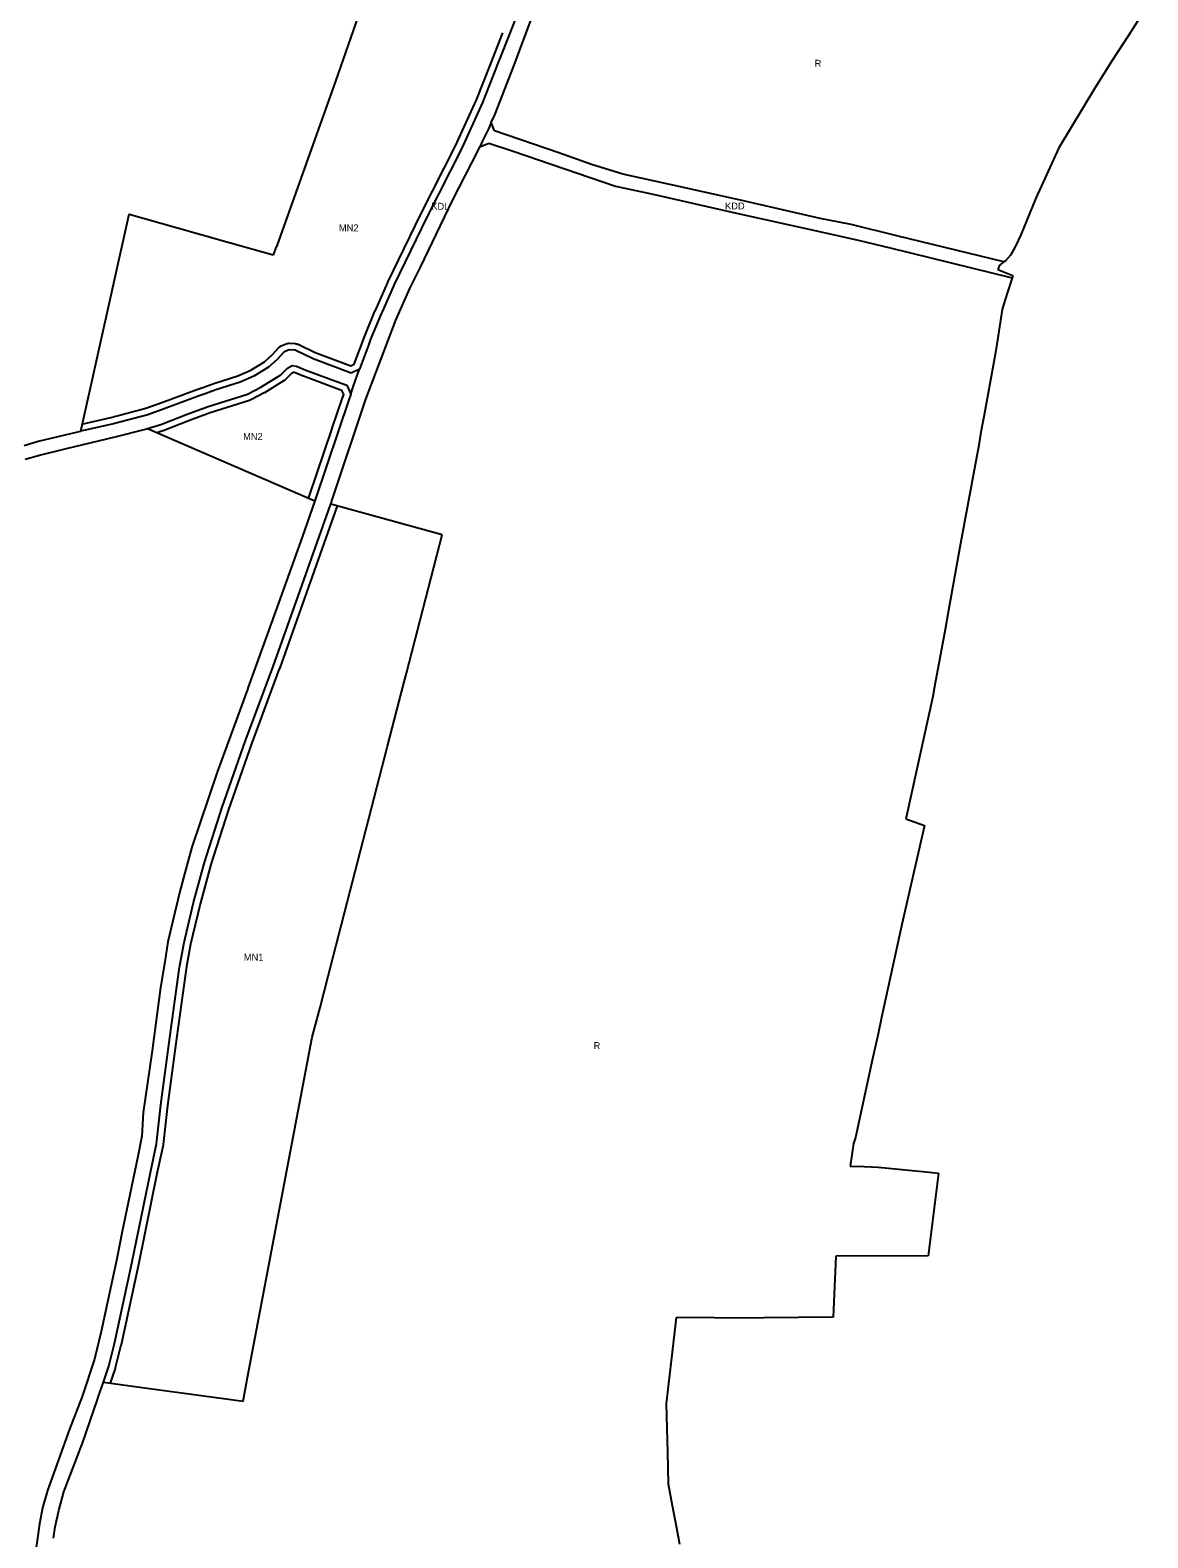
# Model space of a CAD drawing. Extents: x 7435758 to 7439981, y 5550649 to 5554049.
# Drawn here: x 7439010 to 7439847, y 5551717 to 5552845 of the extents above; entities that cross this region are included whole.
import ezdxf

# ---------------------------------------------------------------- set-up
doc = ezdxf.new("R2010")
doc.units = 0
for name, color, linetype in [('linie_rozgraniczające', 7, 'Continuous'), ('linie_zabudowy_nieprzekraczalne', 7, 'Continuous'), ('oznaczenia_przeznaczen', 7, 'Continuous')]:
    doc.layers.add(name, color=color, linetype=linetype)

msp = doc.modelspace()

# ---------------------------------------------------------------- linework, layer by layer
at = {"layer": 'linie_rozgraniczające'}
for p, q in [((7439255.67, 5552855.96), (7439238.89, 5552807.33)), ((7439846.87, 5552864.2), (7439832.42, 5552841.4)), ((7439373.25, 5552853.51), (7439368.77, 5552842.02)), ((7439372.45, 5552819.32), (7439385.2, 5552853.46)), ((7439368.77, 5552842.02), (7439362.63, 5552826.25)), ((7439832.42, 5552841.4), (7439820.12, 5552822.79)), ((7439362.63, 5552826.25), (7439359.42, 5552818.09)), ((7439820.12, 5552822.79), (7439807.09, 5552802.1)), ((7439359.39, 5552818.03), (7439348.82, 5552791.18)), ((7439358.05, 5552781.97), (7439372.45, 5552819.32)), ((7439359.42, 5552818.09), (7439359.39, 5552818.03)), ((7439238.89, 5552807.33), (7439194.84, 5552684.02)), ((7439807.09, 5552802.1), (7439780.21, 5552757.37)), ((7439348.82, 5552791.18), (7439333.03, 5552756.68)), ((7439355.33, 5552776.17), (7439353.22, 5552771.66)), ((7439355.33, 5552776.17), (7439358.05, 5552781.97)), ((7439357.88, 5552770.07), (7439355.33, 5552776.17)), ((7439353.22, 5552771.66), (7439348.92, 5552762.48)), ((7439405.86, 5552753.7), (7439357.88, 5552770.07)), ((7439333.03, 5552756.68), (7439307.34, 5552706.02)), ((7439326.48, 5552717.99), (7439346.06, 5552756.38)), ((7439346.06, 5552756.38), (7439346.82, 5552758.01)), ((7439348.92, 5552762.48), (7439346.82, 5552758.01)), ((7439346.82, 5552758.01), (7439353.66, 5552760.88)), ((7439353.66, 5552760.88), (7439371.66, 5552754.81)), ((7439371.66, 5552754.81), (7439448.33, 5552728.55)), ((7439430.38, 5552744.9), (7439405.86, 5552753.7)), ((7439780.21, 5552757.37), (7439762.9, 5552719.61)), ((7439453.79, 5552737.73), (7439430.38, 5552744.9)), ((7439489.1, 5552729.79), (7439453.79, 5552737.73)), ((7439541.85, 5552718.18), (7439489.1, 5552729.79)), ((7439448.33, 5552728.55), (7439475.43, 5552722.78)), ((7439475.43, 5552722.78), (7439538.91, 5552708.48)), ((7439762.9, 5552719.61), (7439751.79, 5552692.12)), ((7439084.13, 5552707.39), (7439047.85, 5552545.11)), ((7439084.3, 5552707.35), (7439084.13, 5552707.39)), ((7439120.5, 5552697.25), (7439084.3, 5552707.35)), ((7439302.31, 5552668.03), (7439326.48, 5552717.99)), ((7439538.91, 5552708.48), (7439601.13, 5552694.65)), ((7439601.56, 5552704.46), (7439541.85, 5552718.18)), ((7439159.19, 5552686.27), (7439120.5, 5552697.25)), ((7439307.34, 5552706.02), (7439282.47, 5552654.61)), ((7439624.86, 5552699.99), (7439601.56, 5552704.46)), ((7439658.94, 5552691.58), (7439624.86, 5552699.99)), ((7439160.28, 5552685.96), (7439159.19, 5552686.27)), ((7439192.13, 5552676.93), (7439160.28, 5552685.96)), ((7439601.13, 5552694.65), (7439630.13, 5552688.33)), ((7439630.13, 5552688.33), (7439653.9, 5552682.42)), ((7439739.05, 5552671.95), (7439658.94, 5552691.58)), ((7439751.79, 5552692.12), (7439747.68, 5552683.73)), ((7439194.41, 5552683.35), (7439192.13, 5552676.93)), ((7439194.79, 5552683.23), (7439194.41, 5552683.35)), ((7439194.84, 5552684.02), (7439194.79, 5552683.23)), ((7439653.9, 5552682.42), (7439745.3, 5552660.06)), ((7439743.95, 5552677.01), (7439740.25, 5552672.84)), ((7439747.68, 5552683.73), (7439743.95, 5552677.01)), ((7439294.45, 5552652.07), (7439302.31, 5552668.03)), ((7439735.82, 5552669.57), (7439734.52, 5552666.24)), ((7439734.52, 5552666.24), (7439745.81, 5552661.68)), ((7439739.05, 5552671.95), (7439735.82, 5552669.57)), ((7439740.25, 5552672.84), (7439739.05, 5552671.95)), ((7439281.86, 5552653.23), (7439273.61, 5552634.66)), ((7439282.47, 5552654.61), (7439281.86, 5552653.23)), ((7439283.89, 5552628.31), (7439294.45, 5552652.07)), ((7439745.3, 5552660.06), (7439739.94, 5552642.98)), ((7439745.81, 5552661.68), (7439745.3, 5552660.06)), ((7439739.94, 5552642.98), (7439737.83, 5552636.3)), ((7439272.92, 5552633.12), (7439265.1, 5552614.05)), ((7439270.86, 5552594.17), (7439283.89, 5552628.31)), ((7439273.61, 5552634.66), (7439272.92, 5552633.12)), ((7439737.83, 5552636.3), (7439733.73, 5552610.29)), ((7439203.82, 5552606.02), (7439200.03, 5552604.44)), ((7439208.5, 5552605.8), (7439203.82, 5552606.02)), ((7439209.08, 5552605.53), (7439208.5, 5552605.8)), ((7439221.95, 5552599.44), (7439209.08, 5552605.53)), ((7439263.49, 5552609.73), (7439256.74, 5552591.63)), ((7439265.1, 5552614.05), (7439263.49, 5552609.73)), ((7439733.73, 5552610.29), (7439732.52, 5552602.7)), ((7439195.18, 5552598.97), (7439188.51, 5552593.21)), ((7439200.03, 5552604.44), (7439195.18, 5552598.97)), ((7439202.85, 5552592.48), (7439206.42, 5552594.45)), ((7439206.42, 5552594.45), (7439209.49, 5552593.96)), ((7439250.39, 5552588.68), (7439221.95, 5552599.44)), ((7439732.52, 5552602.7), (7439724.05, 5552555.91)), ((7439177.61, 5552586.48), (7439167.44, 5552582.01)), ((7439188.51, 5552593.21), (7439177.61, 5552586.48)), ((7439182.92, 5552578.27), (7439197.78, 5552587.4)), ((7439197.78, 5552587.4), (7439202.85, 5552592.48)), ((7439209.49, 5552593.96), (7439216.51, 5552591)), ((7439216.51, 5552591), (7439243.72, 5552580.94)), ((7439256.74, 5552591.63), (7439250.39, 5552588.68)), ((7439251.83, 5552577.78), (7439253.71, 5552583.51)), ((7439253.71, 5552583.51), (7439254.99, 5552586.94)), ((7439254.99, 5552586.94), (7439256.74, 5552591.63)), ((7439261.45, 5552569.09), (7439270.86, 5552594.17)), ((7439136.7, 5552571.72), (7439110.5, 5552561.93)), ((7439141.23, 5552573.29), (7439136.7, 5552571.72)), ((7439149.31, 5552576.09), (7439141.23, 5552573.29)), ((7439167.44, 5552582.01), (7439149.31, 5552576.09)), ((7439160.15, 5552569.02), (7439172.98, 5552572.99)), ((7439172.98, 5552572.99), (7439182.92, 5552578.27)), ((7439243.72, 5552580.94), (7439247.25, 5552579.56)), ((7439247.25, 5552579.56), (7439250.28, 5552573.03)), ((7439250.28, 5552573.03), (7439248.61, 5552567.93)), ((7439250.28, 5552573.03), (7439251.83, 5552577.78)), ((7439110.5, 5552561.93), (7439098.29, 5552557.58)), ((7439127.62, 5552557.86), (7439143.41, 5552563.78)), ((7439143.41, 5552563.78), (7439160.15, 5552569.02)), ((7439236.62, 5552494.68), (7439261.45, 5552569.09)), ((7439248.61, 5552567.93), (7439240.92, 5552545.74)), ((7439071.68, 5552550.51), (7439048.02, 5552545.14)), ((7439098.29, 5552557.58), (7439071.68, 5552550.51)), ((7439098, 5552547.13), (7439108.03, 5552550.16)), ((7439108.03, 5552550.16), (7439127.62, 5552557.86)), ((7439723.14, 5552550.9), (7439721.71, 5552542.98)), ((7439724.05, 5552555.91), (7439723.14, 5552550.9)), ((7439045.53, 5552544.58), (7439016.18, 5552537.5)), ((7439036.4, 5552531.93), (7439074.9, 5552541.3)), ((7439047.85, 5552545.11), (7439045.53, 5552544.58)), ((7439048.02, 5552545.14), (7439047.85, 5552545.11)), ((7439074.9, 5552541.3), (7439095.6, 5552546.41)), ((7439095.6, 5552546.41), (7439098, 5552547.13)), ((7439098, 5552547.13), (7439223.31, 5552493)), ((7439240.92, 5552545.74), (7439223.62, 5552493.86)), ((7439721.71, 5552542.98), (7439720.23, 5552534.81)), ((7439016.18, 5552537.5), (7439005.75, 5552534.23)), ((7439006.47, 5552524.22), (7439017.3, 5552527.29)), ((7439017.3, 5552527.29), (7439036.4, 5552531.93)), ((7439720.23, 5552534.81), (7439706.53, 5552461.04)), ((7439223.31, 5552493), (7439213.81, 5552465.85)), ((7439223.62, 5552493.86), (7439223.31, 5552493)), ((7439235.18, 5552490.61), (7439236.62, 5552494.68)), ((7439212.38, 5552426.06), (7439235.01, 5552490.13)), ((7439235.01, 5552490.13), (7439235.18, 5552490.61)), ((7439318.72, 5552467.71), (7439235.18, 5552490.61)), ((7439213.81, 5552465.85), (7439193.8, 5552410.21)), ((7439291.88, 5552363.98), (7439318.71, 5552467.68)), ((7439318.71, 5552467.68), (7439318.72, 5552467.71)), ((7439706.53, 5552461.04), (7439697.5, 5552409.68)), ((7439196.06, 5552380.36), (7439212.38, 5552426.06)), ((7439193.8, 5552410.21), (7439173.45, 5552353.58)), ((7439697.5, 5552409.68), (7439695.23, 5552396.78)), ((7439695.23, 5552396.78), (7439687.52, 5552355.35)), ((7439192.05, 5552369.12), (7439196.06, 5552380.36)), ((7439179.57, 5552335.6), (7439192.05, 5552369.12)), ((7439289.99, 5552356.65), (7439291.88, 5552363.98)), ((7439172.85, 5552351.93), (7439150.24, 5552289.94)), ((7439173.45, 5552353.58), (7439172.85, 5552351.93)), ((7439277.81, 5552309.57), (7439289.99, 5552356.65)), ((7439685.87, 5552346.55), (7439666.38, 5552258.33)), ((7439687.52, 5552355.35), (7439685.87, 5552346.55)), ((7439171.14, 5552312.98), (7439179.57, 5552335.6)), ((7439153.93, 5552263.71), (7439171.14, 5552312.98)), ((7439233.26, 5552137.35), (7439277.81, 5552309.57)), ((7439150.24, 5552289.94), (7439131.28, 5552233.82)), ((7439140.65, 5552222.42), (7439153.93, 5552263.71)), ((7439666.38, 5552258.33), (7439665.66, 5552255.08)), ((7439679.7, 5552250.02), (7439662.83, 5552175.92)), ((7439665.66, 5552255.08), (7439679.7, 5552250.02)), ((7439131.28, 5552233.82), (7439126.07, 5552214.59)), ((7439132.54, 5552192.46), (7439140.65, 5552222.42)), ((7439126.07, 5552214.59), (7439121.99, 5552199.58)), ((7439121.99, 5552199.58), (7439113.2, 5552162.89)), ((7439126.17, 5552165.69), (7439132.54, 5552192.46)), ((7439125.39, 5552162.39), (7439126.17, 5552165.69)), ((7439662.83, 5552175.92), (7439647.6, 5552106.42)), ((7439113.2, 5552162.89), (7439110.94, 5552147.95)), ((7439122.24, 5552145.25), (7439125.39, 5552162.39)), ((7439110.94, 5552147.95), (7439107.81, 5552128.81)), ((7439121.82, 5552142.23), (7439122.24, 5552145.25)), ((7439114.69, 5552091.3), (7439121.82, 5552142.23)), ((7439227.2, 5552113.92), (7439233.26, 5552137.35)), ((7439107.81, 5552128.81), (7439101.33, 5552079.71)), ((7439221.4, 5552091.51), (7439227.2, 5552113.92)), ((7439647.6, 5552106.42), (7439644.91, 5552094.13)), ((7439107.95, 5552041.09), (7439114.69, 5552091.3)), ((7439173.02, 5551836.94), (7439221.4, 5552091.51)), ((7439644.91, 5552094.13), (7439640.32, 5552073.23)), ((7439101.33, 5552079.71), (7439094.93, 5552035.3)), ((7439640.32, 5552073.23), (7439628.11, 5552016.58)), ((7439094.93, 5552035.3), (7439093.83, 5552017.55)), ((7439104.88, 5552011.74), (7439107.95, 5552041.09)), ((7439093.83, 5552017.55), (7439090.8, 5552002.32)), ((7439100.49, 5551991.53), (7439104.88, 5552011.74)), ((7439626.62, 5552011.92), (7439624.07, 5551995.04)), ((7439628.11, 5552016.58), (7439626.62, 5552011.92)), ((7439090.8, 5552002.32), (7439079.14, 5551946.24)), ((7439086.41, 5551922.49), (7439100.49, 5551991.53)), ((7439624.07, 5551995.04), (7439634.57, 5551994.74)), ((7439634.57, 5551994.74), (7439645.07, 5551994.44)), ((7439645.07, 5551994.44), (7439662.93, 5551992.58)), ((7439662.93, 5551992.58), (7439680.8, 5551990.73)), ((7439680.8, 5551990.73), (7439690.17, 5551989.77)), ((7439690.17, 5551989.77), (7439682.55, 5551927.9)), ((7439079.14, 5551946.24), (7439075.02, 5551925.75)), ((7439075.02, 5551925.75), (7439063.3, 5551871.23)), ((7439073.35, 5551862.28), (7439086.41, 5551922.49)), ((7439613.43, 5551927.75), (7439611.4, 5551881.93)), ((7439682.55, 5551927.9), (7439613.43, 5551927.75)), ((7439493.83, 5551881.78), (7439490.28, 5551851.69)), ((7439522.57, 5551881.56), (7439493.83, 5551881.78)), ((7439551.31, 5551881.34), (7439522.57, 5551881.56)), ((7439559.42, 5551881.42), (7439551.31, 5551881.34)), ((7439585.41, 5551881.67), (7439559.42, 5551881.42)), ((7439611.4, 5551881.93), (7439585.41, 5551881.67)), ((7439063.3, 5551871.23), (7439058.28, 5551850.58)), ((7439069.1, 5551845.37), (7439073.35, 5551862.28)), ((7439058.28, 5551850.58), (7439049.25, 5551822.61)), ((7439490.28, 5551851.69), (7439486.73, 5551821.61)), ((7439065, 5551833.49), (7439066.74, 5551838.52)), ((7439066.74, 5551838.52), (7439069.1, 5551845.37)), ((7439061.33, 5551822.82), (7439065, 5551833.49)), ((7439065, 5551833.49), (7439097.85, 5551829.02)), ((7439097.85, 5551829.02), (7439169.66, 5551819.25)), ((7439169.66, 5551819.25), (7439173.02, 5551836.94)), ((7439049.25, 5551822.61), (7439039.56, 5551798.25)), ((7439049.1, 5551787.07), (7439060.75, 5551821.16)), ((7439060.75, 5551821.16), (7439061.33, 5551822.82)), ((7439486.73, 5551821.61), (7439486.22, 5551817.3)), ((7439486.22, 5551817.3), (7439486.73, 5551798.99)), ((7439039.56, 5551798.25), (7439023.32, 5551752.4)), ((7439486.73, 5551798.99), (7439487.23, 5551780.67)), ((7439046.89, 5551781.28), (7439048.37, 5551785.17)), ((7439048.37, 5551785.17), (7439049.1, 5551787.07)), ((7439035.46, 5551751.39), (7439046.89, 5551781.28)), ((7439487.23, 5551780.67), (7439487.87, 5551757.21)), ((7439023.32, 5551752.4), (7439019.43, 5551739.22)), ((7439031.64, 5551737.24), (7439035.46, 5551751.39)), ((7439487.87, 5551757.21), (7439490.9, 5551741.18)), ((7439019.43, 5551739.22), (7439017.3, 5551727.41)), ((7439028.84, 5551725.06), (7439031.64, 5551737.24)), ((7439490.9, 5551741.18), (7439494.09, 5551724.26)), ((7439017.3, 5551727.41), (7439013.95, 5551704.23)), ((7439027.73, 5551716.53), (7439028.84, 5551725.06)), ((7439494.09, 5551724.26), (7439496.38, 5551712.14))]:
    msp.add_line(p, q, dxfattribs=at)
at = {"layer": 'linie_zabudowy_nieprzekraczalne'}
for points in [[(7439048.86, 5552550.46), (7439070.49, 5552555.37), (7439096.81, 5552562.36), (7439108.79, 5552566.63), (7439134.95, 5552576.41), (7439135.06, 5552576.45), (7439139.59, 5552578.02), (7439147.72, 5552580.83), (7439165.66, 5552586.68), (7439175.28, 5552590.92), (7439185.54, 5552597.26), (7439191.66, 5552602.53), (7439196.29, 5552607.76), (7439196.83, 5552608.28), (7439197.44, 5552608.72), (7439198.11, 5552609.06), (7439201.91, 5552610.64), (7439202.61, 5552610.87), (7439203.32, 5552610.99), (7439204.05, 5552611.01), (7439208.73, 5552610.79), (7439209.38, 5552610.72), (7439210.02, 5552610.56), (7439210.63, 5552610.32), (7439211.22, 5552610.05), (7439223.48, 5552604.23), (7439223.73, 5552604.13), (7439224.09, 5552603.97), (7439224.28, 5552603.89), (7439250.19, 5552594.1), (7439252.77, 5552595.3), (7439260.42, 5552615.8), (7439260.48, 5552615.95), (7439268.3, 5552635.02), (7439268.35, 5552635.15), (7439268.36, 5552635.16), (7439277.9, 5552656.64), (7439277.97, 5552656.79), (7439302.84, 5552708.2), (7439302.88, 5552708.28), (7439328.52, 5552758.85), (7439344.22, 5552793.14), (7439354.7, 5552819.75), (7439363.97, 5552843.3)], [(7439218.73, 5552495.03), (7439218.88, 5552495.47), (7439236.17, 5552547.32), (7439236.19, 5552547.38), (7439243.87, 5552569.53), (7439244.92, 5552572.72), (7439243.56, 5552575.63), (7439241.94, 5552576.26), (7439214.78, 5552586.31), (7439214.57, 5552586.39), (7439208.11, 5552589.12), (7439207.34, 5552589.24), (7439205.88, 5552588.44), (7439201.31, 5552583.87), (7439201.14, 5552583.7), (7439200.42, 5552583.16), (7439185.54, 5552574.01), (7439185.27, 5552573.85), (7439175.33, 5552568.58), (7439174.88, 5552568.37), (7439174.46, 5552568.22), (7439161.64, 5552564.25), (7439145.04, 5552559.05), (7439129.41, 5552553.19), (7439109.86, 5552545.51), (7439109.48, 5552545.37), (7439105.13, 5552544.06)], [(7439240, 5552489.23), (7439217.09, 5552424.39), (7439217.09, 5552424.38), (7439196.76, 5552367.44), (7439196.74, 5552367.39), (7439196.73, 5552367.37), (7439175.84, 5552311.28), (7439158.67, 5552262.12), (7439145.45, 5552221), (7439137.38, 5552191.23), (7439130.28, 5552161.36), (7439127.18, 5552144.45), (7439119.64, 5552090.64), (7439112.91, 5552040.49), (7439109.86, 5552011.22), (7439109.82, 5552010.96), (7439109.77, 5552010.67), (7439105.38, 5551990.5), (7439091.31, 5551921.49), (7439091.3, 5551921.43), (7439078.24, 5551861.22), (7439078.23, 5551861.18), (7439078.2, 5551861.06), (7439073.95, 5551844.15), (7439073.9, 5551843.95), (7439073.83, 5551843.74), (7439071.83, 5551837.94)], [(7439071.82, 5551837.93), (7439070.04, 5551832.76)]]:
    msp.add_lwpolyline(points, dxfattribs=at)

# ---------------------------------------------------------------- texts
at = {"layer": 'oznaczenia_przeznaczen'}
for s, p in [('R', (7439597.46, 5552818)), ('KDL', (7439310.49, 5552710.98)), ('KDD', (7439530.38, 5552711.18)), ('MN2', (7439241.33, 5552694.78)), ('MN2', (7439169.6, 5552538.69)), ('MN1', (7439170.15, 5552148.92)), ('R', (7439431.95, 5552082.7))]:
    msp.add_text(s, height=5.2, dxfattribs=at).set_placement(p)

doc.saveas('drawing.dxf')
